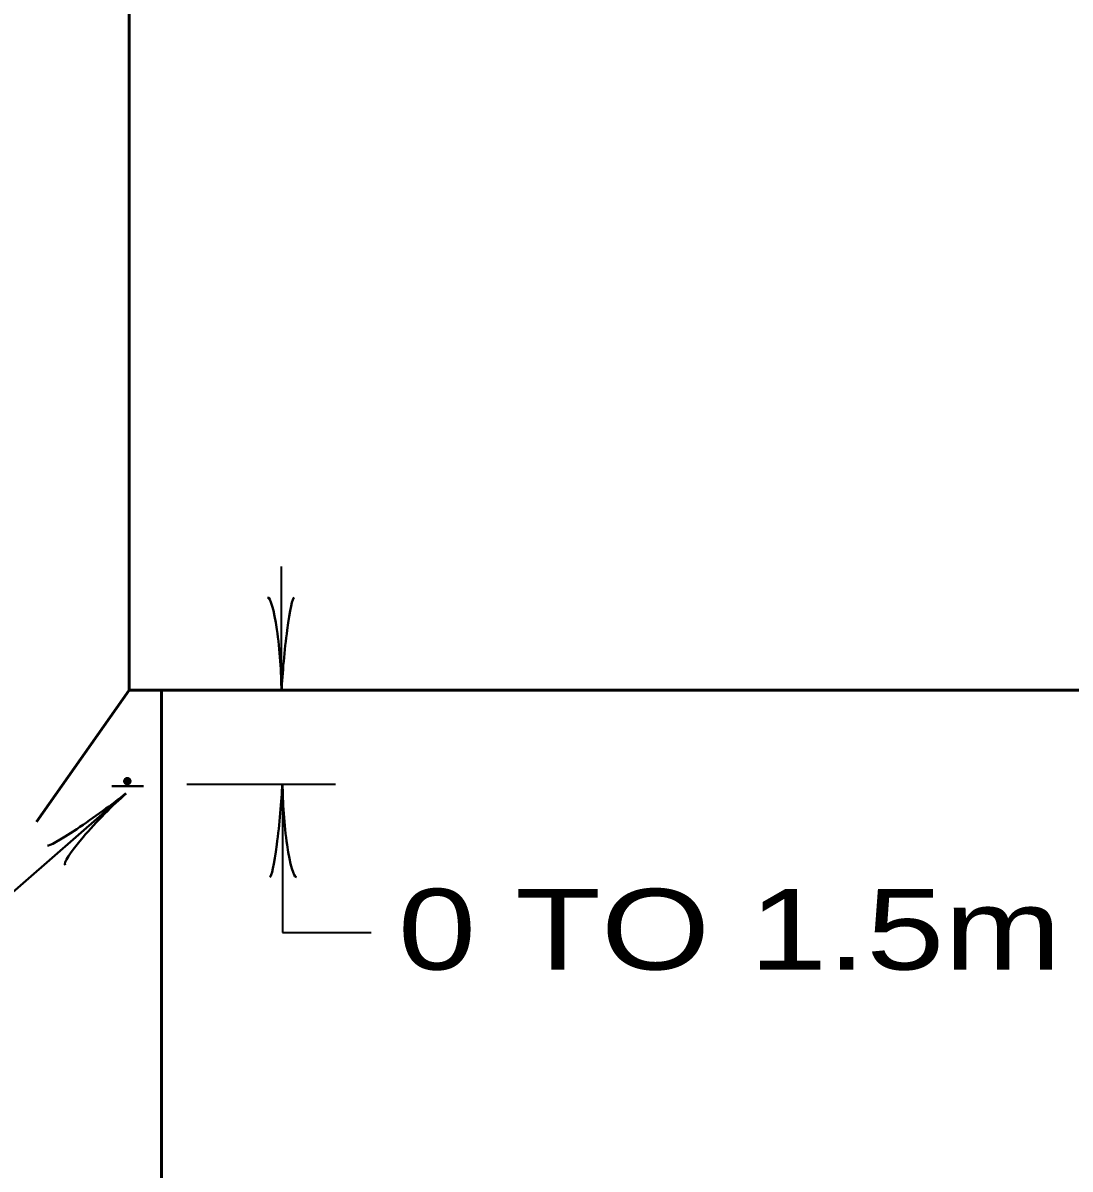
# Model space of a CAD drawing. Extents: x -1843 to -987, y 1073 to 1617.
# Drawn here: x -1478.76 to -1439.88, y 1345.62 to 1388.2 of the extents above; entities that cross this region are included whole.
import ezdxf
from ezdxf.enums import TextEntityAlignment as Align

# ---------------------------------------------------------------- set-up
doc = ezdxf.new("R2010")
doc.units = 0
doc.header["$LTSCALE"] = 1.2
doc.layers.add('1', color=7, linetype='Continuous', lineweight=53)

msp = doc.modelspace()

# ---------------------------------------------------------------- linework, layer by layer
at = {"layer": '1'}
for p, q in [((-1474.82, 1461.213), (-1474.82, 1363.413)), ((-1474.82, 1363.413), (-1478.251, 1358.513)), ((-1474.82, 1363.413), (-1435.197, 1363.413)), ((-1473.62, 1303.454), (-1473.62, 1363.413))]:
    msp.add_line(p, q, dxfattribs=at)
at = {"layer": '1', "lineweight": 35}
for p, q in [((-1469.157, 1363.399), (-1469.157, 1368.009)), ((-1472.677, 1359.917), (-1467.15, 1359.917)), ((-1469.127, 1359.917), (-1469.127, 1354.405)), ((-1469.127, 1354.405), (-1465.833, 1354.405))]:
    msp.add_line(p, q, dxfattribs=at)
at = {"layer": '1', "lineweight": 40}
for p, q in [((-1475.455, 1359.841), (-1474.288, 1359.841)), ((-1479.526, 1355.555), (-1474.942, 1359.569))]:
    msp.add_line(p, q, dxfattribs=at)
msp.add_circle((-1474.884, 1360.024), 0.12, dxfattribs=at)
for centre, major_axis, ratio, start_param, end_param in [((-1469.488, 1364.709), (0.187, -2.143), 0.122415, 0.896353, 3.141593), ((-1468.903, 1364.744), (0.211, 2.108), 0.07063, 6.282307, 8.559703), ((-1469.381, 1358.572), (-0.211, -2.108), 0.07063, 6.282307, 8.559703), ((-1468.795, 1358.607), (-0.187, 2.143), 0.122415, 0.896353, 3.141593), ((-1476.12, 1358.874), (1.725, 1.23), 0.07063, 3.140715, 5.41811), ((-1475.708, 1358.457), (1.489, 1.553), 0.122415, 0.896353, 3.141593)]:
    msp.add_ellipse(centre, major_axis=major_axis, ratio=ratio, start_param=start_param, end_param=end_param, dxfattribs=at)
msp.add_spline([(-1474.89, 1359.915), (-1474.875, 1360.133), (-1474.906, 1359.918), (-1474.887, 1360.137), (-1474.921, 1359.926), (-1474.902, 1360.141), (-1474.929, 1359.93), (-1474.925, 1360.137), (-1474.929, 1359.915), (-1474.929, 1360.106), (-1474.933, 1359.926), (-1474.936, 1360.102), (-1474.94, 1359.922), (-1474.936, 1360.122), (-1474.94, 1359.934), (-1474.944, 1360.114), (-1474.948, 1359.949), (-1474.956, 1360.006), (-1474.948, 1360.11), (-1474.959, 1359.98), (-1474.952, 1359.926), (-1474.967, 1360.033), (-1474.952, 1360.095), (-1474.963, 1360.087), (-1474.971, 1360.06), (-1474.975, 1360.03), (-1474.975, 1359.987), (-1474.967, 1359.953), (-1474.967, 1359.961), (-1474.979, 1360.014), (-1474.986, 1360.041), (-1474.975, 1360.072), (-1474.959, 1360.087), (-1474.944, 1360.106), (-1474.979, 1359.995), (-1474.864, 1360.122), (-1474.864, 1360.06), (-1474.879, 1360.026), (-1474.883, 1359.984), (-1474.887, 1359.941), (-1474.883, 1359.922), (-1474.852, 1360.125), (-1474.867, 1359.918), (-1474.841, 1360.125), (-1474.856, 1359.926), (-1474.821, 1360.118), (-1474.848, 1359.926), (-1474.818, 1360.11), (-1474.841, 1359.93), (-1474.829, 1359.957), (-1474.825, 1359.945), (-1474.814, 1359.968), (-1474.821, 1359.945), (-1474.833, 1359.934), (-1474.798, 1359.972), (-1474.791, 1360.045), (-1474.802, 1360.087), (-1474.814, 1359.976), (-1474.81, 1360.033), (-1474.802, 1360.076), (-1474.814, 1359.972), (-1474.825, 1359.991), (-1474.818, 1360.037), (-1474.783, 1360.01), (-1474.825, 1359.995), (-1474.802, 1359.957), (-1474.829, 1359.945), (-1474.844, 1359.938), (-1474.864, 1359.93), (-1474.875, 1359.926), (-1474.894, 1359.926), (-1474.917, 1359.938), (-1474.99, 1360.003), (-1474.994, 1360.022), (-1474.982, 1360.072), (-1474.967, 1360.095), (-1474.962, 1360.111)], degree=3, dxfattribs=at)

# ---------------------------------------------------------------- texts
at = {"layer": '1', "width": 1.3}
msp.add_text('0 TO 1.5m', height=3, dxfattribs=at).set_placement((-1452.519, 1353.028), align=Align.CENTER)

doc.saveas('drawing.dxf')
